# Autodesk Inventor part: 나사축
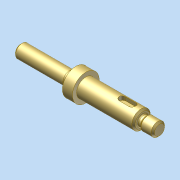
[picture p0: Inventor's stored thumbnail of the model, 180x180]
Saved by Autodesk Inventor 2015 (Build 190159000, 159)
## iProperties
Created: 2026-09
Part Number: 나사축
Material: 일반
Document SubType Name: Modeling
Designer: SCD-A06
Density: 1 g/cm^3
Appearance: 기본값
Author: SCD-A06
Author: jhkim
Creation Date: 2026-08-27
Sending System: Autodesk Inventor 2027
Preprocessor: ST-DEVELOPER v20.1
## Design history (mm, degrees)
node "나사축1"
node "솔리드1"
node "기준1"
